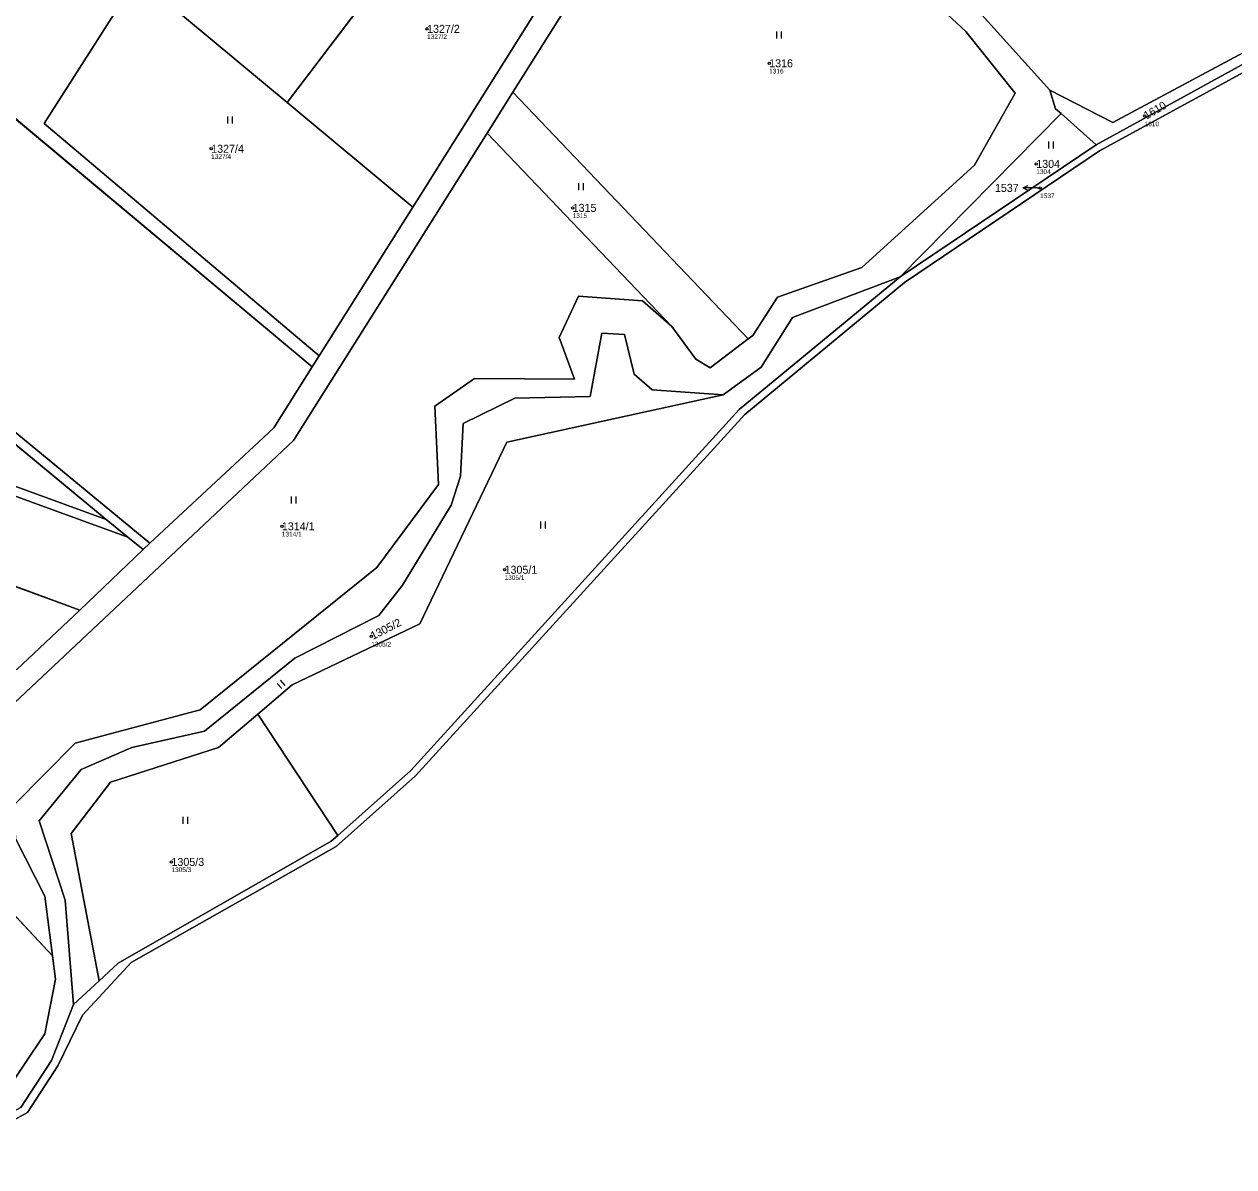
# Model space of a CAD drawing. Extents: x -658203 to -653176, y -1156738 to -1151709.
# Drawn here: x -654168.6 to -653911.6, y -1154180.9 to -1153938.2 of the extents above; entities that cross this region are included whole.
import ezdxf

# ---------------------------------------------------------------- set-up
doc = ezdxf.new("R2010")
doc.units = 0
for name, color, linetype in [('Vrstva 1', 7, 'Continuous'), ('Vrstva 2', 7, 'Continuous'), ('Vrstva 3', 7, 'Continuous'), ('Vrstva 50', 7, 'Continuous'), ('Vrstva 51', 7, 'Continuous'), ('Vrstva 53', 7, 'Continuous'), ('Vrstva 7', 7, 'Continuous')]:
    doc.layers.add(name, color=color, linetype=linetype)

msp = doc.modelspace()

# ---------------------------------------------------------------- linework, layer by layer
at = {"layer": 'Vrstva 1'}
for p, q in [((-654064.77, -1153952.6), (-654022.42, -1153885.32)), ((-654107.4, -1154010.96), (-654234.93, -1153904.47)), ((-654082.53, -1153915.09), (-654112.72, -1153954.81)), ((-653950.65, -1153952.18), (-653978.81, -1153920.92)), ((-654287.64, -1153928.21), (-654141.91, -1154048.41)), ((-654144.59, -1153928.26), (-654164.38, -1153959.26)), ((-654112.72, -1153954.81), (-654144.59, -1153928.26)), ((-654112.72, -1153954.81), (-654086.04, -1153977.03)), ((-654070.25, -1153961.32), (-654064.77, -1153952.6)), ((-654014.76, -1154005), (-654064.77, -1153952.6)), ((-653948.25, -1153957.16), (-653982.47, -1153991.84)), ((-653940.84, -1153963.77), (-653948.25, -1153957.16)), ((-654164.38, -1153959.26), (-654105.91, -1154008.59)), ((-654070.25, -1153961.32), (-654111.35, -1154026.61)), ((-654030.96, -1154002.42), (-654070.25, -1153961.32)), ((-653982.47, -1153991.84), (-653940.84, -1153963.77)), ((-654105.91, -1154008.59), (-654086.04, -1153977.03)), ((-654151.16, -1154043.36), (-654222.11, -1153984.84)), ((-654105.91, -1154008.59), (-654107.4, -1154010.96)), ((-654146.55, -1154047.16), (-654208.51, -1154024.62)), ((-654111.35, -1154026.61), (-654193.18, -1154103.42)), ((-654156.78, -1154062.66), (-654235.19, -1154033.94)), ((-654146.55, -1154047.16), (-654151.16, -1154043.36)), ((-654143.35, -1154049.79), (-654146.55, -1154047.16)), ((-654143.35, -1154049.79), (-654156.78, -1154062.66)), ((-654141.91, -1154048.41), (-654143.35, -1154049.79)), ((-654156.78, -1154062.66), (-654170.19, -1154075.24)), ((-654118.98, -1154084.75), (-654101.98, -1154110.53)), ((-654085.42, -1154097.87), (-654102.32, -1154112.88)), ((-654101.98, -1154110.53), (-654086.41, -1154096.75)), ((-654193.18, -1154103.42), (-654162.59, -1154136.11)), ((-654103.34, -1154111.74), (-654101.98, -1154110.53)), ((-654102.32, -1154112.88), (-654145.84, -1154137.54)), ((-654152.66, -1154141.38), (-654148.61, -1154137.62)), ((-654158.09, -1154146.41), (-654152.66, -1154141.38)), ((-654167.89, -1154169.4), (-654207.79, -1154191.19))]:
    msp.add_line(p, q, dxfattribs=at)
for points in [[(-653985.04, -1153919.01), (-653982.15, -1153926.97), (-653968.53, -1153939.72), (-653958.04, -1153952.81), (-653966.65, -1153968.12), (-653990.62, -1153989.84), (-654008.51, -1153996.17), (-654013.81, -1154004.27), (-654014.76, -1154005)], [(-654086.04, -1153977.03), (-654083.35, -1153972.76), (-654080.66, -1153968.48), (-654058.79, -1153933.74)], [(-653899.46, -1153938.77), (-653937.3, -1153959.03), (-653950.65, -1153952.18)], [(-653899.46, -1153938.77), (-653902.03, -1153942.49), (-653940.84, -1153963.77)], [(-653900.89, -1153943.66), (-653940.13, -1153965.06), (-653981.57, -1153993.05), (-654015.45, -1154021.06), (-654085.42, -1154097.87)], [(-653950.65, -1153952.18), (-653949.43, -1153956.11), (-653948.25, -1153957.16)], [(-654086.41, -1154096.75), (-654016.65, -1154020.02), (-653982.47, -1153991.84)], [(-653982.47, -1153991.84), (-654005.36, -1154000.45), (-654011.97, -1154011.04), (-654020.1, -1154016.89)], [(-654162.59, -1154136.11), (-654164.22, -1154123.39), (-654170.37, -1154111.28), (-654170.64, -1154103.92), (-654157.8, -1154090.94), (-654131.19, -1154083.85), (-654093.68, -1154053.58), (-654080.57, -1154035.92), (-654081.38, -1154019.33), (-654072.95, -1154013.44), (-654051.69, -1154013.57), (-654054.9, -1154004.74), (-654050.84, -1153995.93), (-654037.24, -1153996.95), (-654030.96, -1154002.42)], [(-654014.76, -1154005), (-654022.83, -1154011.17), (-654025.9, -1154009.33), (-654030.96, -1154002.42)], [(-654241.43, -1154005.39), (-654234.16, -1154012.3), (-654233.3, -1154012.67), (-654214.99, -1154015.18), (-654206.89, -1154023.08), (-654151.16, -1154043.36)], [(-654020.1, -1154016.89), (-654035.13, -1154015.83), (-654038.98, -1154012.49), (-654041.02, -1154004.12), (-654045.83, -1154003.79), (-654048.31, -1154017.24), (-654064.32, -1154017.6), (-654075.35, -1154023), (-654075.86, -1154034.17), (-654077.84, -1154040.38), (-654088.23, -1154057.36), (-654093.26, -1154063.79), (-654111.1, -1154072.87), (-654130.31, -1154088.33), (-654145.71, -1154091.85), (-654156.47, -1154096.48), (-654165.44, -1154107.38), (-654159.87, -1154124.25), (-654158.09, -1154146.41)], [(-654107.4, -1154010.96), (-654115.58, -1154023.95), (-654118.8, -1154026.95), (-654141.91, -1154048.41)], [(-654020.1, -1154016.89), (-654066.04, -1154026.96), (-654084.52, -1154065.58), (-654111.65, -1154078.5), (-654118.98, -1154084.75)], [(-654152.66, -1154141.38), (-654158.62, -1154110.07), (-654150.29, -1154099.17), (-654127.32, -1154091.85), (-654118.98, -1154084.75)], [(-654148.61, -1154137.62), (-654133.03, -1154128.71), (-654103.34, -1154111.74)], [(-654162.59, -1154136.11), (-654161.95, -1154141.05), (-654164.22, -1154152.69), (-654173.14, -1154165.96), (-654194.27, -1154172.65), (-654204.93, -1154179.74)], [(-654145.84, -1154137.54), (-654156.23, -1154148.69), (-654161.48, -1154159.48), (-654167.89, -1154169.4)], [(-654158.09, -1154146.41), (-654162.83, -1154158.31), (-654169.31, -1154168.32)]]:
    msp.add_lwpolyline(points, dxfattribs=at)
at = {"layer": 'Vrstva 3'}
for p, q in [((-654008.65, -1153941.22), (-654008.65, -1153939.72)), ((-654007.65, -1153941.22), (-654007.65, -1153939.72)), ((-654125.32, -1153959.25), (-654125.32, -1153957.75)), ((-654124.32, -1153959.25), (-654124.32, -1153957.75)), ((-653950.91, -1153964.57), (-653950.91, -1153963.07)), ((-653949.91, -1153964.57), (-653949.91, -1153963.07)), ((-654050.77, -1153973.41), (-654050.77, -1153971.91)), ((-654049.77, -1153973.41), (-654049.77, -1153971.91)), ((-654111.83, -1154039.98), (-654111.83, -1154038.48)), ((-654110.83, -1154039.98), (-654110.83, -1154038.48)), ((-654058.84, -1154045.29), (-654058.84, -1154043.79)), ((-654057.84, -1154045.29), (-654057.84, -1154043.79)), ((-654113.88, -1154079.32), (-654114.88, -1154078.21)), ((-654113.14, -1154078.65), (-654114.14, -1154077.54)), ((-654134.8, -1154108.06), (-654134.8, -1154106.56)), ((-654133.8, -1154108.06), (-654133.8, -1154106.56))]:
    msp.add_line(p, q, dxfattribs=at)
at = {"layer": 'Vrstva 50'}
for centre in [(-654082.99, -1153939.15), (-654010.3, -1153946.47), (-653930.53, -1153957.69), (-654128.87, -1153964.63), (-653953.55, -1153967.84), (-653952.72, -1153972.94), (-654052.06, -1153977.18), (-654113.85, -1154044.84), (-654066.53, -1154054.07), (-654094.86, -1154068.22), (-654137.31, -1154116.14)]:
    msp.add_circle(centre, 0.25, dxfattribs=at)
at = {"layer": 'Vrstva 51'}
for points in [[(-654004, -1153756.79), (-654022.41, -1153778.36), (-654004.41, -1153800.12), (-654002.24, -1153806.85), (-654012.55, -1153839.5), (-654025.73, -1153881.23), (-654039.66, -1153903.4), (-654058.79, -1153933.74), (-654080.66, -1153968.48), (-654083.35, -1153972.76), (-654086.04, -1153977.03), (-654105.91, -1154008.59), (-654107.4, -1154010.96), (-654115.58, -1154023.95), (-654118.8, -1154026.95), (-654141.91, -1154048.41), (-654143.35, -1154049.79), (-654156.78, -1154062.66), (-654170.19, -1154075.24)], [(-654329.82, -1154231.75), (-654269.61, -1154175.16), (-654237.56, -1154145.07), (-654193.18, -1154103.42), (-654111.35, -1154026.61), (-654070.25, -1153961.32), (-654064.77, -1153952.6), (-654022.42, -1153885.32), (-654021.11, -1153883.25), (-653996.47, -1153805.14), (-654015.37, -1153782.13), (-654015.28, -1153774.6)], [(-654169.31, -1154168.32), (-654162.83, -1154158.31), (-654158.09, -1154146.41), (-654159.87, -1154124.25), (-654165.44, -1154107.38), (-654156.47, -1154096.48), (-654145.71, -1154091.85), (-654130.31, -1154088.33), (-654111.1, -1154072.87), (-654093.26, -1154063.79), (-654088.23, -1154057.36), (-654077.84, -1154040.38), (-654075.86, -1154034.17), (-654075.35, -1154023), (-654064.32, -1154017.6), (-654048.31, -1154017.24), (-654045.83, -1154003.79), (-654041.02, -1154004.12), (-654038.98, -1154012.49), (-654035.13, -1154015.83), (-654020.1, -1154016.89), (-654011.97, -1154011.04), (-654005.36, -1154000.45), (-653982.47, -1153991.84), (-653948.25, -1153957.16), (-653949.43, -1153956.11), (-653950.65, -1153952.18), (-653978.81, -1153920.92)], [(-653982.15, -1153926.97), (-653968.53, -1153939.72), (-653958.04, -1153952.81), (-653966.65, -1153968.12), (-653990.62, -1153989.84), (-654008.51, -1153996.17), (-654013.81, -1154004.27), (-654014.76, -1154005), (-654022.83, -1154011.17), (-654025.9, -1154009.33), (-654030.96, -1154002.42), (-654037.24, -1153996.95), (-654050.84, -1153995.93), (-654054.9, -1154004.74), (-654051.69, -1154013.57), (-654072.95, -1154013.44), (-654081.38, -1154019.33), (-654080.57, -1154035.92), (-654093.68, -1154053.58), (-654131.19, -1154083.85), (-654157.8, -1154090.94), (-654170.64, -1154103.92)], [(-653902.03, -1153942.49), (-653940.84, -1153963.77), (-653982.47, -1153991.84), (-654016.65, -1154020.02), (-654086.41, -1154096.75), (-654101.98, -1154110.53), (-654103.34, -1154111.74), (-654133.03, -1154128.71), (-654148.61, -1154137.62), (-654152.66, -1154141.38), (-654158.09, -1154146.41), (-654162.83, -1154158.31), (-654169.31, -1154168.32), (-654208.24, -1154189.13)], [(-654207.79, -1154191.19), (-654167.89, -1154169.4), (-654161.48, -1154159.48), (-654156.23, -1154148.69), (-654145.84, -1154137.54), (-654102.32, -1154112.88), (-654085.42, -1154097.87), (-654015.45, -1154021.06), (-653981.57, -1153993.05), (-653940.13, -1153965.06), (-653900.89, -1153943.66)], [(-654208.51, -1154024.62), (-654146.55, -1154047.16), (-654151.16, -1154043.36), (-654206.89, -1154023.08)], [(-654170.37, -1154111.28), (-654164.22, -1154123.39), (-654162.59, -1154136.11), (-654161.95, -1154141.05), (-654164.22, -1154152.69), (-654173.14, -1154165.96)]]:
    msp.add_lwpolyline(points, dxfattribs=at)
for points in [[(-654144.59, -1153928.26), (-654208.89, -1153874.7), (-654234.93, -1153904.47), (-654107.4, -1154010.96), (-654105.91, -1154008.59), (-654164.38, -1153959.26)], [(-653899.46, -1153938.77), (-653894.11, -1153931.05), (-653946.46, -1153873.3), (-653946.46, -1153877.99), (-653955.28, -1153891.99), (-653977.86, -1153894.05), (-653978.81, -1153920.92), (-653950.65, -1153952.18), (-653937.3, -1153959.03)], [(-654082.53, -1153915.09), (-654117.03, -1153885.08), (-654144.59, -1153928.26), (-654112.72, -1153954.81)], [(-653994.01, -1153915.3), (-654022.42, -1153885.32), (-654064.77, -1153952.6), (-654014.76, -1154005), (-654013.81, -1154004.27), (-654008.51, -1153996.17), (-653990.62, -1153989.84), (-653966.65, -1153968.12), (-653958.04, -1153952.81), (-653968.53, -1153939.72), (-653982.15, -1153926.97), (-653985.04, -1153919.01)], [(-654141.91, -1154048.41), (-654118.8, -1154026.95), (-654115.58, -1154023.95), (-654107.4, -1154010.96), (-654234.93, -1153904.47), (-654236.62, -1153906.46), (-654263.39, -1153906.35), (-654269.56, -1153906.33), (-654287.64, -1153928.21)], [(-654083.35, -1153972.76), (-654080.66, -1153968.48), (-654058.79, -1153933.74), (-654082.53, -1153915.09), (-654112.72, -1153954.81), (-654086.04, -1153977.03)], [(-654287.64, -1153928.21), (-654288.91, -1153929.75), (-654287.29, -1153931.06), (-654273.13, -1153942.77), (-654260.43, -1153953.25), (-654247.73, -1153963.72), (-654234.76, -1153974.42), (-654222.11, -1153984.84), (-654151.16, -1154043.36), (-654146.55, -1154047.16), (-654143.35, -1154049.79), (-654141.91, -1154048.41)], [(-654105.91, -1154008.59), (-654086.04, -1153977.03), (-654112.72, -1153954.81), (-654144.59, -1153928.26), (-654164.38, -1153959.26)], [(-653937.3, -1153959.03), (-653950.65, -1153952.18), (-653949.43, -1153956.11), (-653948.25, -1153957.16), (-653940.84, -1153963.77), (-653902.03, -1153942.49), (-653899.46, -1153938.77)], [(-654014.76, -1154005), (-654064.77, -1153952.6), (-654070.25, -1153961.32), (-654030.96, -1154002.42), (-654025.9, -1154009.33), (-654022.83, -1154011.17)], [(-653940.84, -1153963.77), (-653948.25, -1153957.16), (-653982.47, -1153991.84)], [(-654157.8, -1154090.94), (-654131.19, -1154083.85), (-654093.68, -1154053.58), (-654080.57, -1154035.92), (-654081.38, -1154019.33), (-654072.95, -1154013.44), (-654051.69, -1154013.57), (-654054.9, -1154004.74), (-654050.84, -1153995.93), (-654037.24, -1153996.95), (-654030.96, -1154002.42), (-654070.25, -1153961.32), (-654111.35, -1154026.61), (-654193.18, -1154103.42), (-654162.59, -1154136.11), (-654164.22, -1154123.39), (-654170.37, -1154111.28), (-654170.64, -1154103.92)], [(-654234.16, -1154012.3), (-654233.3, -1154012.67), (-654214.99, -1154015.18), (-654206.89, -1154023.08), (-654151.16, -1154043.36), (-654222.11, -1153984.84), (-654241.43, -1154005.39)], [(-654118.98, -1154084.75), (-654101.98, -1154110.53), (-654086.41, -1154096.75), (-654016.65, -1154020.02), (-653982.47, -1153991.84), (-654005.36, -1154000.45), (-654011.97, -1154011.04), (-654020.1, -1154016.89), (-654066.04, -1154026.96), (-654084.52, -1154065.58), (-654111.65, -1154078.5)], [(-654093.26, -1154063.79), (-654111.1, -1154072.87), (-654130.31, -1154088.33), (-654145.71, -1154091.85), (-654156.47, -1154096.48), (-654165.44, -1154107.38), (-654159.87, -1154124.25), (-654158.09, -1154146.41), (-654152.66, -1154141.38), (-654158.62, -1154110.07), (-654150.29, -1154099.17), (-654127.32, -1154091.85), (-654118.98, -1154084.75), (-654111.65, -1154078.5), (-654084.52, -1154065.58), (-654066.04, -1154026.96), (-654020.1, -1154016.89), (-654035.13, -1154015.83), (-654038.98, -1154012.49), (-654041.02, -1154004.12), (-654045.83, -1154003.79), (-654048.31, -1154017.24), (-654064.32, -1154017.6), (-654075.35, -1154023), (-654075.86, -1154034.17), (-654077.84, -1154040.38), (-654088.23, -1154057.36)], [(-654229.07, -1154017.14), (-654235.19, -1154033.94), (-654156.78, -1154062.66), (-654143.35, -1154049.79), (-654146.55, -1154047.16), (-654208.51, -1154024.62), (-654210.62, -1154030.23), (-654217.03, -1154027.86), (-654214.93, -1154022.28)], [(-654240.99, -1154049.73), (-654170.19, -1154075.24), (-654156.78, -1154062.66), (-654235.19, -1154033.94)], [(-654133.03, -1154128.71), (-654103.34, -1154111.74), (-654101.98, -1154110.53), (-654118.98, -1154084.75), (-654127.32, -1154091.85), (-654150.29, -1154099.17), (-654158.62, -1154110.07), (-654152.66, -1154141.38), (-654148.61, -1154137.62)], [(-654162.59, -1154136.11), (-654193.18, -1154103.42), (-654237.56, -1154145.07), (-654204.93, -1154179.74), (-654194.27, -1154172.65), (-654173.14, -1154165.96), (-654164.22, -1154152.69), (-654161.95, -1154141.05)]]:
    msp.add_lwpolyline(points, close=True, dxfattribs=at)
at = {"layer": 'Vrstva 53'}
msp.add_lwpolyline([(-654207.79, -1154191.19), (-654167.89, -1154169.4), (-654161.48, -1154159.48), (-654156.23, -1154148.69), (-654145.84, -1154137.54), (-654102.32, -1154112.88), (-654085.42, -1154097.87), (-654015.45, -1154021.06), (-653981.57, -1153993.05), (-653940.13, -1153965.06), (-653900.89, -1153943.66), (-653895.07, -1153938.82), (-653891.14, -1153929.8), (-653889.99, -1153921.95), (-653893.63, -1153838.24), (-653883.43, -1153810), (-653857.5, -1153768.81), (-653850.4, -1153761.09), (-653836.61, -1153754.73), (-653825.13, -1153752.32), (-653790.39, -1153756.92), (-653769.48, -1153754.77), (-653716.83, -1153762.5), (-653672.73, -1153777.43)], dxfattribs=at)
at = {"layer": 'Vrstva 7'}
for p, q in [((-653956.33, -1153972.94), (-653955.33, -1153972.44)), ((-653953.33, -1153972.94), (-653956.33, -1153972.94)), ((-653956.33, -1153972.94), (-653955.33, -1153973.44)), ((-653953.33, -1153972.94), (-653952.72, -1153972.94))]:
    msp.add_line(p, q, dxfattribs=at)

# ---------------------------------------------------------------- texts
at = {"layer": 'Vrstva 2'}
for s, p in [('1327/2', (-654082.99, -1153940)), ('1316', (-654010.3, -1153947.32)), ('1327/4', (-654128.87, -1153965.48)), ('1304', (-653953.55, -1153968.69)), ('1537', (-653962.34, -1153973.79)), ('1315', (-654052.06, -1153978.03)), ('1314/1', (-654113.85, -1154045.69)), ('1305/1', (-654066.53, -1154054.92)), ('1305/3', (-654137.31, -1154116.99))]:
    msp.add_text(s, height=1.7, dxfattribs=at).set_placement(p)
for s, rotation, p in [('1610', 30, (-653930.1, -1153958.43)), ('1305/2', 27, (-654094.47, -1154068.98))]:
    msp.add_text(s, height=1.7, rotation=rotation, dxfattribs=at).set_placement(p)
at = {"layer": 'Vrstva 50'}
for s, p in [('1327/2', (-654082.99, -1153941.31)), ('1316', (-654010.3, -1153948.63)), ('1610', (-653930.53, -1153959.85)), ('1327/4', (-654128.87, -1153966.79)), ('1304', (-653953.55, -1153970)), ('1537', (-653952.72, -1153975.1)), ('1315', (-654052.06, -1153979.34)), ('1314/1', (-654113.85, -1154047)), ('1305/1', (-654066.53, -1154056.23)), ('1305/2', (-654094.86, -1154070.38)), ('1305/3', (-654137.31, -1154118.3))]:
    msp.add_text(s, height=1, dxfattribs=at).set_placement(p)

doc.saveas('drawing.dxf')
